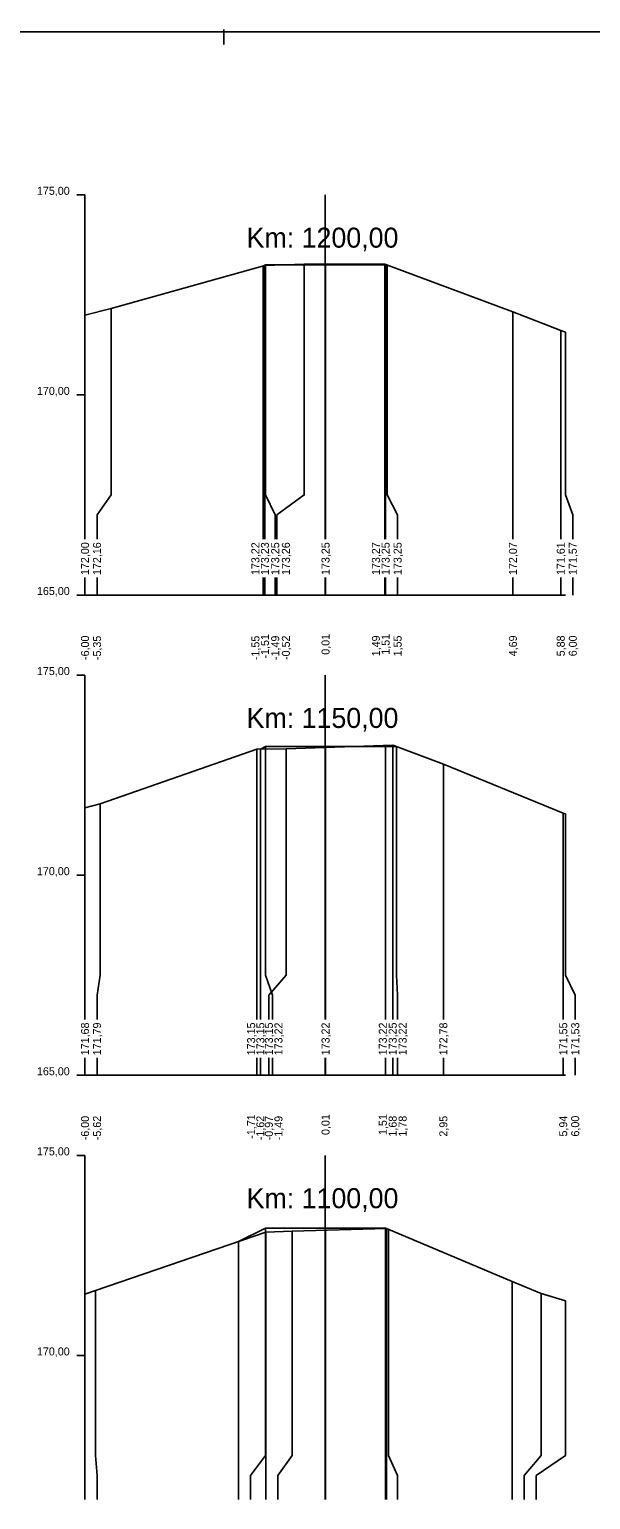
# Model space of a CAD drawing. Extents: x -614174 to -599765, y -1185887 to -1181080.
# Drawn here: x -601026.82 to -601012.8, y -1184419.94 to -1184383.21 of the extents above; entities that cross this region are included whole.
import ezdxf

# ---------------------------------------------------------------- set-up
doc = ezdxf.new("R2010")
doc.units = 0
for name, color, linetype in [('11', 7, 'Continuous'), ('16', 7, 'Continuous'), ('21', 7, 'Continuous'), ('28', 7, 'Continuous'), ('59', 7, 'Continuous'), ('8', 7, 'Continuous'), ('návrh', 7, 'Continuous')]:
    doc.layers.add(name, color=color, linetype=linetype)

msp = doc.modelspace()

# ---------------------------------------------------------------- linework, layer by layer
for points in [[(-601025.427, -1184390.346), (-601024.774, -1184390.187), (-601020.933, -1184389.111), (-601019.949, -1184389.079), (-601017.941, -1184389.072), (-601014.739, -1184390.268), (-601013.544, -1184390.734), (-601013.427, -1184390.771)], [(-601020.976, -1184389.123), (-601020.919, -1184389.095), (-601019.419, -1184389.095), (-601017.919, -1184389.095), (-601017.88, -1184389.095)], [(-601020.976, -1184389.123), (-601020.976, -1184389.123), (-601020.976, -1184389.123)], [(-601020.919, -1184389.095), (-601020.919, -1184389.095), (-601020.919, -1184389.095)], [(-601019.419, -1184389.095), (-601019.419, -1184389.095), (-601019.419, -1184389.095)], [(-601017.919, -1184389.095), (-601017.919, -1184389.095), (-601017.919, -1184389.095)], [(-601025.427, -1184402.663), (-601025.047, -1184402.556), (-601021.135, -1184401.191), (-601020.401, -1184401.188), (-601017.742, -1184401.092), (-601016.476, -1184401.565), (-601013.482, -1184402.796), (-601013.427, -1184402.812)], [(-601021.047, -1184401.191), (-601020.919, -1184401.127), (-601019.419, -1184401.127), (-601017.919, -1184401.127), (-601017.65, -1184401.127)], [(-601020.919, -1184401.127), (-601020.919, -1184401.127), (-601020.919, -1184401.127)], [(-601019.419, -1184401.127), (-601019.419, -1184401.127), (-601019.419, -1184401.127)], [(-601017.919, -1184401.127), (-601017.919, -1184401.127), (-601017.919, -1184401.127)], [(-601021.047, -1184401.191), (-601021.047, -1184401.191), (-601021.047, -1184401.191)], [(-601025.427, -1184414.807), (-601025.168, -1184414.716), (-601020.911, -1184413.263), (-601020.25, -1184413.239), (-601017.897, -1184413.174), (-601014.756, -1184414.495), (-601014.031, -1184414.794), (-601013.427, -1184414.979)], [(-601021.595, -1184413.497), (-601020.919, -1184413.159), (-601019.419, -1184413.159), (-601017.919, -1184413.159), (-601017.846, -1184413.195)], [(-601020.919, -1184413.159), (-601020.919, -1184413.159), (-601020.919, -1184413.159)], [(-601019.419, -1184413.159), (-601019.419, -1184413.159), (-601019.419, -1184413.159)], [(-601017.919, -1184413.159), (-601017.919, -1184413.159), (-601017.919, -1184413.159)], [(-601021.595, -1184413.497), (-601021.595, -1184413.497), (-601021.595, -1184413.496)]]:
    msp.add_lwpolyline(points)
at = {"layer": '11'}
for points in [[(-601020.976, -1184389.123), (-601020.976, -1184394.842), (-601020.976, -1184395.342), (-601020.976, -1184395.944)], [(-601020.933, -1184389.111), (-601020.933, -1184394.842), (-601020.933, -1184395.342), (-601020.933, -1184395.944)], [(-601020.919, -1184389.095), (-601020.919, -1184394.842), (-601020.676, -1184395.342), (-601020.676, -1184395.944)], [(-601019.949, -1184389.079), (-601019.949, -1184394.842), (-601020.633, -1184395.342), (-601020.633, -1184395.944)], [(-601019.419, -1184389.095), (-601019.419, -1184394.842), (-601019.419, -1184395.342), (-601019.419, -1184395.944)], [(-601017.941, -1184389.072), (-601017.941, -1184394.842), (-601017.941, -1184395.342), (-601017.941, -1184395.944)], [(-601017.919, -1184389.095), (-601017.919, -1184394.842), (-601017.919, -1184395.342), (-601017.919, -1184395.944)], [(-601017.88, -1184389.095), (-601017.88, -1184394.842), (-601017.619, -1184395.342), (-601017.619, -1184395.944)], [(-601025.427, -1184390.346), (-601025.427, -1184394.842), (-601025.427, -1184395.342), (-601025.427, -1184395.944)], [(-601024.774, -1184390.187), (-601024.774, -1184394.842), (-601025.127, -1184395.342), (-601025.127, -1184395.944)], [(-601014.739, -1184390.268), (-601014.739, -1184394.842), (-601014.739, -1184395.342), (-601014.739, -1184395.944)], [(-601013.544, -1184390.734), (-601013.544, -1184394.842), (-601013.544, -1184395.342), (-601013.544, -1184395.944)], [(-601013.427, -1184390.771), (-601013.427, -1184394.842), (-601013.244, -1184395.342), (-601013.244, -1184395.944)], [(-601025.427, -1184396.902), (-601025.427, -1184397.342)], [(-601025.127, -1184396.902), (-601025.127, -1184397.342)], [(-601020.976, -1184396.902), (-601020.976, -1184397.342)], [(-601020.933, -1184396.902), (-601020.933, -1184397.342)], [(-601020.676, -1184396.902), (-601020.676, -1184397.342)], [(-601020.633, -1184396.902), (-601020.633, -1184397.342)], [(-601019.419, -1184396.902), (-601019.419, -1184397.342)], [(-601017.941, -1184396.902), (-601017.941, -1184397.342)], [(-601017.919, -1184396.902), (-601017.919, -1184397.342)], [(-601017.619, -1184396.902), (-601017.619, -1184397.342)], [(-601014.739, -1184396.902), (-601014.739, -1184397.342)], [(-601013.544, -1184396.902), (-601013.544, -1184397.342)], [(-601013.244, -1184396.902), (-601013.244, -1184397.342)], [(-601020.919, -1184401.127), (-601020.919, -1184406.842), (-601020.747, -1184407.342), (-601020.747, -1184407.944)], [(-601019.419, -1184401.127), (-601019.419, -1184406.842), (-601019.419, -1184407.342), (-601019.419, -1184407.944)], [(-601017.919, -1184401.127), (-601017.919, -1184406.842), (-601017.919, -1184407.342), (-601017.919, -1184407.944)], [(-601017.742, -1184401.092), (-601017.742, -1184406.842), (-601017.742, -1184407.342), (-601017.742, -1184407.944)], [(-601017.65, -1184401.127), (-601017.65, -1184406.842), (-601017.619, -1184407.342), (-601017.619, -1184407.944)], [(-601021.135, -1184401.191), (-601021.135, -1184406.842), (-601021.135, -1184407.342), (-601021.135, -1184407.944)], [(-601021.047, -1184401.191), (-601021.047, -1184406.842), (-601021.047, -1184407.342), (-601021.047, -1184407.944)], [(-601020.401, -1184401.188), (-601020.401, -1184406.842), (-601020.835, -1184407.342), (-601020.835, -1184407.944)], [(-601016.476, -1184401.565), (-601016.476, -1184406.842), (-601016.476, -1184407.342), (-601016.476, -1184407.944)], [(-601025.047, -1184402.556), (-601025.047, -1184406.842), (-601025.127, -1184407.342), (-601025.127, -1184407.944)], [(-601025.427, -1184402.663), (-601025.427, -1184406.842), (-601025.427, -1184407.342), (-601025.427, -1184407.944)], [(-601013.482, -1184402.796), (-601013.482, -1184406.842), (-601013.482, -1184407.342), (-601013.482, -1184407.944)], [(-601013.427, -1184402.812), (-601013.427, -1184406.842), (-601013.182, -1184407.342), (-601013.182, -1184407.944)], [(-601025.427, -1184408.902), (-601025.427, -1184409.342)], [(-601025.127, -1184408.902), (-601025.127, -1184409.342)], [(-601021.135, -1184408.902), (-601021.135, -1184409.342)], [(-601021.047, -1184408.902), (-601021.047, -1184409.342)], [(-601020.835, -1184408.902), (-601020.835, -1184409.342)], [(-601020.747, -1184408.902), (-601020.747, -1184409.342)], [(-601019.419, -1184408.902), (-601019.419, -1184409.342)], [(-601017.919, -1184408.902), (-601017.919, -1184409.342)], [(-601017.742, -1184408.902), (-601017.742, -1184409.342)], [(-601017.619, -1184408.902), (-601017.619, -1184409.342)], [(-601016.476, -1184408.902), (-601016.476, -1184409.342)], [(-601013.482, -1184408.902), (-601013.482, -1184409.342)], [(-601013.182, -1184408.902), (-601013.182, -1184409.342)], [(-601020.919, -1184413.159), (-601020.919, -1184418.842), (-601021.295, -1184419.342), (-601021.295, -1184419.944)], [(-601020.911, -1184413.263), (-601020.911, -1184418.842), (-601020.911, -1184419.342), (-601020.911, -1184419.944)], [(-601020.25, -1184413.239), (-601020.25, -1184418.842), (-601020.611, -1184419.342), (-601020.611, -1184419.944)], [(-601019.419, -1184413.159), (-601019.419, -1184418.842), (-601019.419, -1184419.342), (-601019.419, -1184419.944)], [(-601017.919, -1184413.159), (-601017.919, -1184418.842), (-601017.919, -1184419.342), (-601017.919, -1184419.944)], [(-601017.897, -1184413.174), (-601017.897, -1184418.842), (-601017.897, -1184419.342), (-601017.897, -1184419.944)], [(-601017.846, -1184413.195), (-601017.846, -1184418.842), (-601017.619, -1184419.342), (-601017.619, -1184419.944)], [(-601021.595, -1184413.497), (-601021.595, -1184418.842), (-601021.595, -1184419.342), (-601021.595, -1184419.944)], [(-601025.168, -1184414.716), (-601025.168, -1184418.842), (-601025.127, -1184419.342), (-601025.127, -1184419.944)], [(-601014.756, -1184414.495), (-601014.756, -1184418.842), (-601014.756, -1184419.342), (-601014.756, -1184419.944)], [(-601025.427, -1184414.807), (-601025.427, -1184418.842), (-601025.427, -1184419.342), (-601025.427, -1184419.944)], [(-601014.031, -1184414.794), (-601014.031, -1184418.842), (-601014.456, -1184419.342), (-601014.456, -1184419.944)], [(-601013.427, -1184414.979), (-601013.427, -1184418.842), (-601014.156, -1184419.342), (-601014.156, -1184419.944)]]:
    msp.add_lwpolyline(points, dxfattribs=at)
at = {"layer": '16'}
for p, q in [((-601025.427, -1184397.342), (-601013.427, -1184397.342)), ((-601025.427, -1184409.342), (-601013.427, -1184409.342))]:
    msp.add_line(p, q, dxfattribs=at)
for points in [[(-601017.88, -1184389.095), (-601017.88, -1184389.095), (-601017.88, -1184389.095)], [(-601017.65, -1184401.127), (-601017.65, -1184401.127), (-601017.65, -1184401.127)], [(-601017.845, -1184413.196), (-601017.846, -1184413.195), (-601017.846, -1184413.195)]]:
    msp.add_lwpolyline(points, dxfattribs=at)
at = {"layer": '21'}
for p, q in [((-601025.627, -1184387.342), (-601025.427, -1184387.342)), ((-601025.627, -1184392.342), (-601025.427, -1184392.342)), ((-601025.627, -1184397.342), (-601025.427, -1184397.342)), ((-601025.627, -1184399.342), (-601025.427, -1184399.342)), ((-601025.627, -1184404.342), (-601025.427, -1184404.342)), ((-601025.627, -1184409.342), (-601025.427, -1184409.342)), ((-601025.627, -1184411.342), (-601025.427, -1184411.342)), ((-601025.627, -1184416.342), (-601025.427, -1184416.342))]:
    msp.add_line(p, q, dxfattribs=at)
at = {"layer": '28'}
for p, q in [((-601019.427, -1184395.944), (-601019.427, -1184387.342)), ((-601019.427, -1184397.342), (-601019.427, -1184396.902)), ((-601019.427, -1184407.944), (-601019.427, -1184399.342)), ((-601019.427, -1184409.342), (-601019.427, -1184408.902)), ((-601019.427, -1184419.944), (-601019.427, -1184411.342))]:
    msp.add_line(p, q, dxfattribs=at)
at = {"layer": '8'}
for p, q in [((-601025.427, -1184395.944), (-601025.427, -1184387.342)), ((-601025.427, -1184397.342), (-601025.427, -1184396.902)), ((-601025.427, -1184407.944), (-601025.427, -1184399.342)), ((-601025.427, -1184409.342), (-601025.427, -1184408.902)), ((-601025.427, -1184419.944), (-601025.427, -1184411.342))]:
    msp.add_line(p, q, dxfattribs=at)
at = {"layer": 'návrh'}
for p, q in [((-601084.957, -1184383.271), (-600937.957, -1184383.271)), ((-601021.957, -1184383.59), (-601021.957, -1184383.209))]:
    msp.add_line(p, q, dxfattribs=at)

# ---------------------------------------------------------------- texts
at = {"layer": '16'}
for s, p in [('172,00', (-601025.327, -1184396.842)), ('172,16', (-601025.027, -1184396.842)), ('173,22', (-601021.071, -1184396.842)), ('173,23', (-601020.833, -1184396.842)), ('173,25', (-601020.576, -1184396.842)), ('173,26', (-601020.31, -1184396.842)), ('173,25', (-601019.319, -1184396.842)), ('173,27', (-601018.06, -1184396.842)), ('173,25', (-601017.819, -1184396.842)), ('173,25', (-601017.519, -1184396.842)), ('172,07', (-601014.639, -1184396.842)), ('171,61', (-601013.444, -1184396.842)), ('171,57', (-601013.144, -1184396.842)), ('171,68', (-601025.327, -1184408.842)), ('171,79', (-601025.027, -1184408.842)), ('173,15', (-601021.177, -1184408.842)), ('173,15', (-601020.947, -1184408.842)), ('173,15', (-601020.735, -1184408.842)), ('173,22', (-601020.495, -1184408.842)), ('173,22', (-601019.319, -1184408.842)), ('173,22', (-601017.889, -1184408.842)), ('173,25', (-601017.642, -1184408.842)), ('173,22', (-601017.394, -1184408.842)), ('172,78', (-601016.376, -1184408.842)), ('171,55', (-601013.382, -1184408.842)), ('171,53', (-601013.082, -1184408.842))]:
    msp.add_text(s, height=0.2, rotation=90, dxfattribs=at).set_placement(p)
at = {"layer": '21'}
for s, p in [('175,00', (-601026.627, -1184387.342)), ('170,00', (-601026.627, -1184392.342)), ('165,00', (-601026.627, -1184397.342)), ('175,00', (-601026.627, -1184399.342)), ('170,00', (-601026.627, -1184404.342)), ('165,00', (-601026.627, -1184409.342)), ('175,00', (-601026.627, -1184411.342)), ('170,00', (-601026.627, -1184416.342))]:
    msp.add_text(s, height=0.2, dxfattribs=at).set_placement(p)
at = {"layer": '28'}
for s, p in [('Km: 1200,00', (-601021.39, -1184388.663)), ('Km: 1150,00', (-601021.39, -1184400.663)), ('Km: 1100,00', (-601021.39, -1184412.663))]:
    msp.add_text(s, height=0.5, dxfattribs=at).set_placement(p)
at = {"layer": '59'}
for s, p in [('-6,00', (-601025.327, -1184398.965)), ('-5,35', (-601025.027, -1184398.968)), ('-1,55', (-601021.071, -1184398.968)), ('-1,51', (-601020.833, -1184398.927)), ('-1,49', (-601020.576, -1184398.966)), ('-0,52', (-601020.31, -1184398.964)), ('0,01', (-601019.319, -1184398.834)), ('1,49', (-601018.06, -1184398.873)), ('1,51', (-601017.819, -1184398.834)), ('1,55', (-601017.519, -1184398.875)), ('4,69', (-601014.639, -1184398.873)), ('5,88', (-601013.444, -1184398.873)), ('6,00', (-601013.144, -1184398.872)), ('-1,71', (-601021.177, -1184410.927)), ('0,01', (-601019.319, -1184410.834)), ('1,51', (-601017.889, -1184410.834)), ('-6,00', (-601025.327, -1184410.965)), ('-5,62', (-601025.027, -1184410.964)), ('-1,62', (-601020.947, -1184410.964)), ('-0,97', (-601020.735, -1184410.966)), ('-1,49', (-601020.495, -1184410.966)), ('1,68', (-601017.642, -1184410.873)), ('1,78', (-601017.394, -1184410.873)), ('2,95', (-601016.376, -1184410.875)), ('5,94', (-601013.382, -1184410.872)), ('6,00', (-601013.082, -1184410.872))]:
    msp.add_text(s, height=0.2, rotation=90, dxfattribs=at).set_placement(p)

doc.saveas('drawing.dxf')
